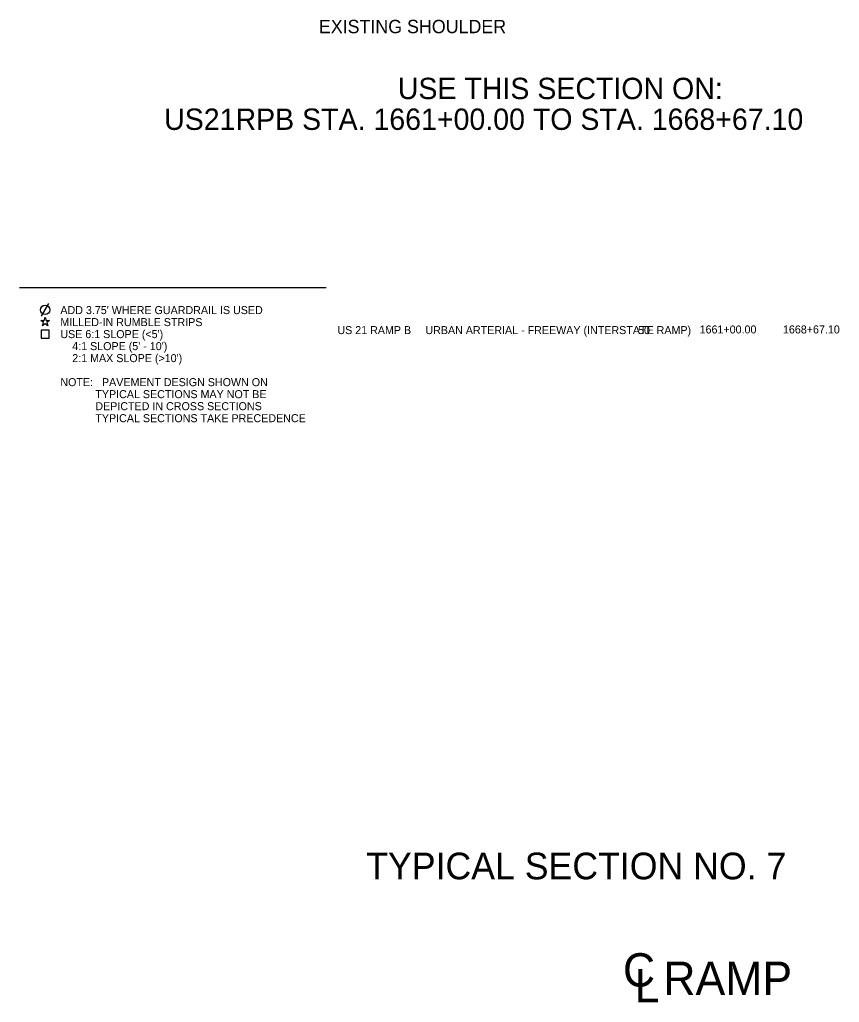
# Model space of a CAD drawing. Extents: x 2003207 to 2014043, y 843846 to 860154.
# Drawn here: x 2013655.8 to 2013717.2, y 844283.7 to 844357.3 of the extents above; entities that cross this region are included whole.
import ezdxf

# ---------------------------------------------------------------- set-up
doc = ezdxf.new("R2010")
doc.units = 0
for name, color, linetype in [('RD_EX_Road_txCode', 7, 'Continuous'), ('RD_SHT_Bndy', 7, 'Continuous'), ('RD_SHT_TX', 7, 'Continuous'), ('RD_TX_Misc1', 7, 'Continuous'), ('RD_TX_TypSect', 7, 'Continuous')]:
    doc.layers.add(name, color=color, linetype=linetype)

msp = doc.modelspace()

# ---------------------------------------------------------------- linework, layer by layer
at = {"layer": 'RD_EX_Road_txCode'}
msp.add_line((2013657.384, 844335.107), (2013657.95, 844336.05), dxfattribs=at)
for points in [[(2013657.334, 844334.786), (2013657.589, 844334.786), (2013657.667, 844335.028), (2013657.746, 844334.786), (2013658, 844334.786), (2013657.794, 844334.637), (2013657.873, 844334.395), (2013657.667, 844334.544), (2013657.462, 844334.395), (2013657.54, 844334.637)], [(2013657.367, 844333.452), (2013657.967, 844333.452), (2013657.967, 844334.052), (2013657.367, 844334.052)]]:
    msp.add_lwpolyline(points, close=True, dxfattribs=at)
msp.add_circle((2013657.667, 844335.578), 0.35, dxfattribs=at)
at = {"layer": 'RD_SHT_Bndy'}
msp.add_line((2013678.754, 844337.242), (2013655.754, 844337.242), dxfattribs=at)

# ---------------------------------------------------------------- texts
at = {"layer": 'RD_EX_Road_txCode'}
for s, height, p in [('USE THIS SECTION ON:', 1.6, (2013684.116, 844351.377)), ('US21RPB STA. 1661+00.00 TO STA. 1668+67.10', 1.6, (2013666.591, 844349.071)), ("ADD 3.75' WHERE GUARDRAIL IS USED", 0.6, (2013658.808, 844335.268)), ('MILLED-IN RUMBLE STRIPS', 0.6, (2013658.808, 844334.368)), ("USE 6:1 SLOPE (<5')", 0.6, (2013658.808, 844333.468)), ("    4:1 SLOPE (5' - 10')", 0.6, (2013658.808, 844332.568)), ("    2:1 MAX SLOPE (>10')", 0.6, (2013658.808, 844331.668)), ('NOTE:   PAVEMENT DESIGN SHOWN ON', 0.6, (2013658.808, 844329.868)), (' TYPICAL SECTIONS MAY NOT BE ', 0.6, (2013661.208, 844328.968)), (' DEPICTED IN CROSS SECTIONS', 0.6, (2013661.208, 844328.068)), (' TYPICAL SECTIONS TAKE PRECEDENCE', 0.6, (2013661.208, 844327.168))]:
    msp.add_text(s, height=height, dxfattribs=at).set_placement(p)
at = {"layer": 'RD_SHT_TX'}
for s, p in [('US 21 RAMP B', (2013679.585, 844333.768)), ('URBAN ARTERIAL - FREEWAY (INTERSTATE RAMP)', (2013686.183, 844333.768)), ('50', (2013702.133, 844333.768)), ('1661+00.00', (2013706.749, 844333.817)), ('1668+67.10', (2013712.999, 844333.817))]:
    msp.add_text(s, height=0.6, dxfattribs=at).set_placement(p)
at = {"layer": 'RD_TX_Misc1'}
for s, p in [('C', (2013701, 844284.875)), ('RAMP', (2013704.027, 844284.246)), ('L', (2013701.878, 844283.694))]:
    msp.add_text(s, height=2.5, dxfattribs=at).set_placement(p)
at = {"layer": 'RD_TX_TypSect'}
for s, height, p in [('EXISTING SHOULDER', 1, (2013678.196, 844356.317)), ('TYPICAL SECTION NO. 7', 2, (2013681.745, 844292.912))]:
    msp.add_text(s, height=height, dxfattribs=at).set_placement(p)

doc.saveas('drawing.dxf')
